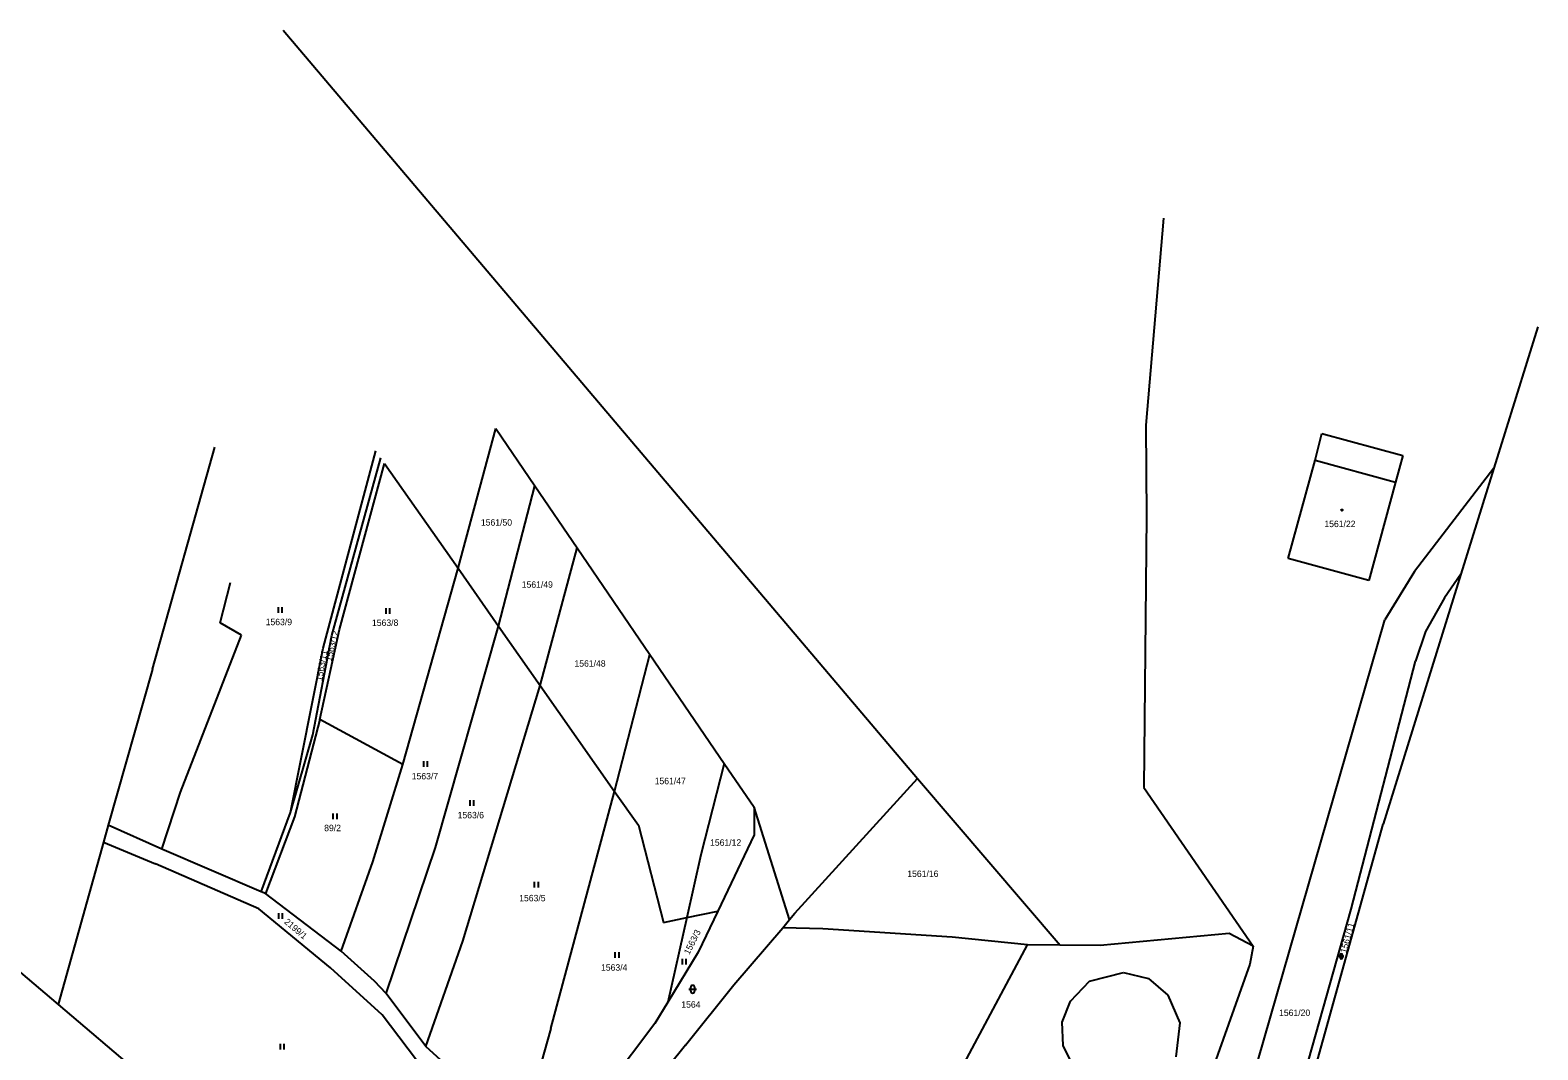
# Model space of a CAD drawing. Extents: x -763296 to -761805, y -1153670 to -1152034.
# Drawn here: x -762549.1 to -762151.3, y -1152302.6 to -1152033.6 of the extents above; entities that cross this region are included whole.
import ezdxf

# ---------------------------------------------------------------- set-up
doc = ezdxf.new("R2010")
doc.units = 0
for name, color, linetype in [('Vrstva 1', 7, 'Continuous'), ('Vrstva 13', 7, 'Continuous'), ('Vrstva 18', 7, 'Continuous'), ('Vrstva 19', 7, 'Continuous'), ('Vrstva 25', 7, 'Continuous'), ('Vrstva 4', 7, 'Continuous'), ('Vrstva 6', 7, 'Continuous')]:
    doc.layers.add(name, color=color, linetype=linetype)

msp = doc.modelspace()

# ---------------------------------------------------------------- linework, layer by layer
at = {"layer": 'Vrstva 1'}
for p, q in [((-762482.31, -1152033.58), (-762315, -1152231)), ((-762250.12, -1152083.15), (-762254.73, -1152137.81)), ((-762254.73, -1152137.81), (-762254.6, -1152161.87)), ((-762426.24, -1152138.68), (-762415.91, -1152153.82)), ((-762210.1, -1152147.03), (-762208.31, -1152139.99)), ((-762208.31, -1152139.99), (-762186.96, -1152145.8)), ((-762186.96, -1152145.8), (-762188.87, -1152152.84)), ((-762455.59, -1152147.9), (-762436.21, -1152175.51)), ((-762217.17, -1152172.93), (-762210.1, -1152147.03)), ((-762162.93, -1152149.16), (-762183.88, -1152176.36)), ((-762415.91, -1152153.82), (-762404.8, -1152170.11)), ((-762188.87, -1152152.84), (-762195.96, -1152178.73)), ((-762254.6, -1152161.87), (-762255.28, -1152233.37)), ((-762404.8, -1152170.11), (-762385.57, -1152198.29)), ((-762195.96, -1152178.73), (-762217.17, -1152172.93)), ((-762436.21, -1152175.51), (-762425.5, -1152190.78)), ((-762183.88, -1152176.36), (-762191.71, -1152189.12)), ((-762171.62, -1152177.12), (-762175.99, -1152183.34)), ((-762175.99, -1152183.34), (-762180.95, -1152192.24)), ((-762230.19, -1152322.79), (-762191.71, -1152189.12)), ((-762425.5, -1152190.78), (-762414.5, -1152206.45)), ((-762180.95, -1152192.24), (-762183.57, -1152200.05)), ((-762385.57, -1152198.29), (-762365.98, -1152227.01)), ((-762200.55, -1152265.44), (-762183.57, -1152200.05)), ((-762414.5, -1152206.45), (-762394.9, -1152234.39)), ((-762365.98, -1152227.01), (-762358.12, -1152238.54)), ((-762347.32, -1152266.53), (-762315, -1152231)), ((-762315, -1152231), (-762277.35, -1152274.92)), ((-762255.28, -1152233.37), (-762226.41, -1152275.23)), ((-762394.9, -1152234.39), (-762388.62, -1152243.34)), ((-762358.12, -1152238.54), (-762358.04, -1152245.84)), ((-762348.75, -1152268.15), (-762358.12, -1152238.54)), ((-762528.55, -1152243.3), (-762529.76, -1152247.77)), ((-762388.62, -1152243.34), (-762381.96, -1152268.97)), ((-762529.76, -1152247.77), (-762541.7, -1152290.61)), ((-762529.76, -1152247.77), (-762516.06, -1152253.46)), ((-762358.04, -1152245.84), (-762367.69, -1152265.96)), ((-762579.17, -1152258.81), (-762541.7, -1152290.61)), ((-762222.86, -1152344.39), (-762200.55, -1152265.44)), ((-762381.96, -1152268.97), (-762375.83, -1152267.68)), ((-762375.83, -1152267.68), (-762367.69, -1152265.96)), ((-762367.69, -1152265.96), (-762372.88, -1152276.78)), ((-762350.53, -1152270.37), (-762348.75, -1152268.15)), ((-762348.75, -1152268.15), (-762347.32, -1152266.53)), ((-762363.41, -1152285.44), (-762350.53, -1152270.37)), ((-762339.94, -1152270.68), (-762350.53, -1152270.37)), ((-762305.88, -1152272.82), (-762339.94, -1152270.68)), ((-762285.97, -1152274.85), (-762305.88, -1152272.82)), ((-762232.79, -1152271.9), (-762266.8, -1152275.01)), ((-762226.41, -1152275.23), (-762232.79, -1152271.9)), ((-762372.88, -1152276.78), (-762380.84, -1152289.95)), ((-762303.34, -1152307.53), (-762285.97, -1152274.85)), ((-762277.35, -1152274.92), (-762285.97, -1152274.85)), ((-762266.8, -1152275.01), (-762277.35, -1152274.92)), ((-762226.41, -1152275.23), (-762227.29, -1152280)), ((-762227.29, -1152280), (-762253.37, -1152353.02)), ((-762274.67, -1152289.77), (-762269.58, -1152284.41)), ((-762269.58, -1152284.41), (-762260.68, -1152282.17)), ((-762260.68, -1152282.17), (-762254.05, -1152283.71)), ((-762254.05, -1152283.71), (-762248.93, -1152288.18)), ((-762376.16, -1152301.32), (-762363.41, -1152285.44)), ((-762248.93, -1152288.18), (-762245.76, -1152295.43)), ((-762541.7, -1152290.61), (-762519.96, -1152309.07)), ((-762380.84, -1152289.95), (-762384.25, -1152295.59)), ((-762276.82, -1152295.29), (-762274.67, -1152289.77)), ((-762384.25, -1152295.59), (-762401.81, -1152318.76)), ((-762276.53, -1152301.44), (-762276.82, -1152295.29)), ((-762245.76, -1152295.43), (-762246.88, -1152304.45)), ((-762376.16, -1152301.32), (-762394.59, -1152324.01)), ((-762273.5, -1152307.66), (-762276.53, -1152301.44))]:
    msp.add_line(p, q, dxfattribs=at)
at = {"layer": 'Vrstva 13'}
for p, q in [((-762151.33, -1152111.83), (-762162.93, -1152149.16)), ((-762162.93, -1152149.16), (-762171.62, -1152177.12)), ((-762171.62, -1152177.12), (-762192.1, -1152243.03)), ((-762215.11, -1152325.64), (-762192.1, -1152243.03))]:
    msp.add_line(p, q, dxfattribs=at)
at = {"layer": 'Vrstva 25'}
for p, q in [((-762483.61, -1152187.31), (-762483.61, -1152185.81)), ((-762482.61, -1152187.31), (-762482.61, -1152185.81)), ((-762455.18, -1152187.58), (-762455.18, -1152186.08)), ((-762454.18, -1152187.58), (-762454.18, -1152186.08)), ((-762445.23, -1152227.95), (-762445.23, -1152226.45)), ((-762444.23, -1152227.95), (-762444.23, -1152226.45)), ((-762433.01, -1152238.18), (-762433.01, -1152236.68)), ((-762432.01, -1152238.18), (-762432.01, -1152236.68)), ((-762469.13, -1152241.68), (-762469.13, -1152240.18)), ((-762468.13, -1152241.68), (-762468.13, -1152240.18)), ((-762416.01, -1152259.73), (-762416.01, -1152258.23)), ((-762415.01, -1152259.73), (-762415.01, -1152258.23)), ((-762483.5, -1152267.98), (-762483.5, -1152266.48)), ((-762482.5, -1152267.98), (-762482.5, -1152266.48)), ((-762394.74, -1152278.34), (-762394.74, -1152276.84)), ((-762393.74, -1152278.34), (-762393.74, -1152276.84)), ((-762377.03, -1152280.02), (-762377.03, -1152278.52)), ((-762376.03, -1152280.02), (-762376.03, -1152278.52)), ((-762203.86, -1152277.9), (-762202.52, -1152277.9)), ((-762203.525, -1152278.235), (-762203.525, -1152277.565)), ((-762202.855, -1152277.565), (-762202.855, -1152278.235)), ((-762375.31, -1152286.58), (-762373.31, -1152286.58)), ((-762374.81, -1152287.08), (-762374.81, -1152286.08)), ((-762373.81, -1152286.08), (-762373.81, -1152287.08)), ((-762483.06, -1152302.46), (-762483.06, -1152300.96)), ((-762482.06, -1152302.46), (-762482.06, -1152300.96))]:
    msp.add_line(p, q, dxfattribs=at)
msp.add_circle((-762203, -1152160.19), 0.175, dxfattribs=at)
for centre, radius, start, end in [((-762203.19, -1152277.565), 0.335, 0, 180), ((-762203.19, -1152278.235), 0.335, 180, 0), ((-762374.31, -1152286.08), 0.5, 0, 180), ((-762374.31, -1152287.08), 0.5, 180, 0)]:
    msp.add_arc(centre, radius, start, end, dxfattribs=at)
at = {"layer": 'Vrstva 4'}
msp.add_line((-762210.1, -1152147.03), (-762188.87, -1152152.84), dxfattribs=at)
at = {"layer": 'Vrstva 6'}
for p, q in [((-762436.21, -1152175.51), (-762426.24, -1152138.68)), ((-762516.83, -1152202.11), (-762500.34, -1152143.6)), ((-762471.78, -1152196.63), (-762457.93, -1152144.56)), ((-762469.5, -1152193.26), (-762456.62, -1152146.43)), ((-762467.49, -1152191.68), (-762455.59, -1152147.9)), ((-762425.5, -1152190.78), (-762415.91, -1152153.82)), ((-762414.5, -1152206.45), (-762404.8, -1152170.11)), ((-762450.78, -1152227.31), (-762436.21, -1152175.51)), ((-762498.95, -1152189.96), (-762496.23, -1152179.32)), ((-762493.3, -1152193.19), (-762498.95, -1152189.96)), ((-762509.43, -1152234.56), (-762493.3, -1152193.19)), ((-762474.56, -1152219.43), (-762469.5, -1152193.26)), ((-762472.63, -1152215.44), (-762467.49, -1152191.68)), ((-762442.13, -1152249.22), (-762425.5, -1152190.78)), ((-762480.42, -1152239.99), (-762471.78, -1152196.63)), ((-762394.9, -1152234.39), (-762385.57, -1152198.29)), ((-762516.83, -1152202.11), (-762528.55, -1152243.3)), ((-762434.92, -1152273.89), (-762414.5, -1152206.45)), ((-762472.63, -1152215.44), (-762479.39, -1152241.08)), ((-762450.78, -1152227.31), (-762472.63, -1152215.44)), ((-762480.42, -1152239.99), (-762474.56, -1152219.43)), ((-762458.68, -1152253.01), (-762450.78, -1152227.31)), ((-762365.98, -1152227.01), (-762372.11, -1152251.16)), ((-762514.38, -1152249.61), (-762509.43, -1152234.56)), ((-762411.77, -1152296.98), (-762394.9, -1152234.39)), ((-762488.11, -1152260.89), (-762480.42, -1152239.99)), ((-762479.39, -1152241.08), (-762486.99, -1152261.37)), ((-762514.38, -1152249.61), (-762528.55, -1152243.3)), ((-762488.11, -1152260.89), (-762514.38, -1152249.61)), ((-762455.2, -1152287.74), (-762442.13, -1152249.22)), ((-762488.75, -1152265.33), (-762516.06, -1152253.46)), ((-762467.01, -1152276.55), (-762458.68, -1152253.01)), ((-762372.11, -1152251.16), (-762375.83, -1152267.68)), ((-762486.99, -1152261.37), (-762488.11, -1152260.89)), ((-762467.01, -1152276.55), (-762486.99, -1152261.37)), ((-762469.88, -1152280.92), (-762488.75, -1152265.33)), ((-762375.83, -1152267.68), (-762380.84, -1152289.95)), ((-762458.27, -1152284.41), (-762467.01, -1152276.55)), ((-762444.73, -1152301.68), (-762434.92, -1152273.89)), ((-762456.19, -1152293.37), (-762469.88, -1152280.92)), ((-762455.2, -1152287.74), (-762458.27, -1152284.41)), ((-762444.73, -1152301.68), (-762455.2, -1152287.74)), ((-762444.95, -1152308.18), (-762456.19, -1152293.37)), ((-762411.77, -1152296.98), (-762417.72, -1152318.29)), ((-762433.24, -1152312.08), (-762444.73, -1152301.68))]:
    msp.add_line(p, q, dxfattribs=at)

# ---------------------------------------------------------------- texts
at = {"layer": 'Vrstva 18'}
for s, p in [('1561/50', (-762430.176, -1152164.28)), ('1561/49', (-762419.403, -1152180.68)), ('1563/9', (-762486.958, -1152190.55)), ('1563/8', (-762458.908, -1152190.75)), ('1561/48', (-762405.493, -1152201.5)), ('1563/7', (-762448.418, -1152231.23)), ('1561/47', (-762384.332, -1152232.5)), ('1563/6', (-762436.318, -1152241.5)), ('89/2', (-762471.524, -1152244.89)), ('1561/12', (-762369.718, -1152248.73)), ('1561/16', (-762317.685, -1152256.97)), ('1563/5', (-762420.075, -1152263.39)), ('1563/4', (-762398.488, -1152281.69)), ('1564', (-762377.302, -1152291.45)), ('1561/20', (-762219.603, -1152293.64))]:
    msp.add_text(s, height=1.7, dxfattribs=at).set_placement(p)
for s, rotation, p in [('1563/12', 76.54716, (-762469.606, -1152200.215)), ('1563/11', 79.52654, (-762472.099, -1152205.377)), ('2199/1', 319.65315, (-762482.218, -1152269.044)), ('1561/11', 74.59911, (-762201.861, -1152277.202)), ('1563/3', 63.42643, (-762375.207, -1152277.613))]:
    msp.add_text(s, height=1.7, rotation=rotation, dxfattribs=at).set_placement(p)
at = {"layer": 'Vrstva 19'}
msp.add_text('1561/22', height=1.7, dxfattribs=at).set_placement((-762207.65, -1152164.68))

doc.saveas('drawing.dxf')
